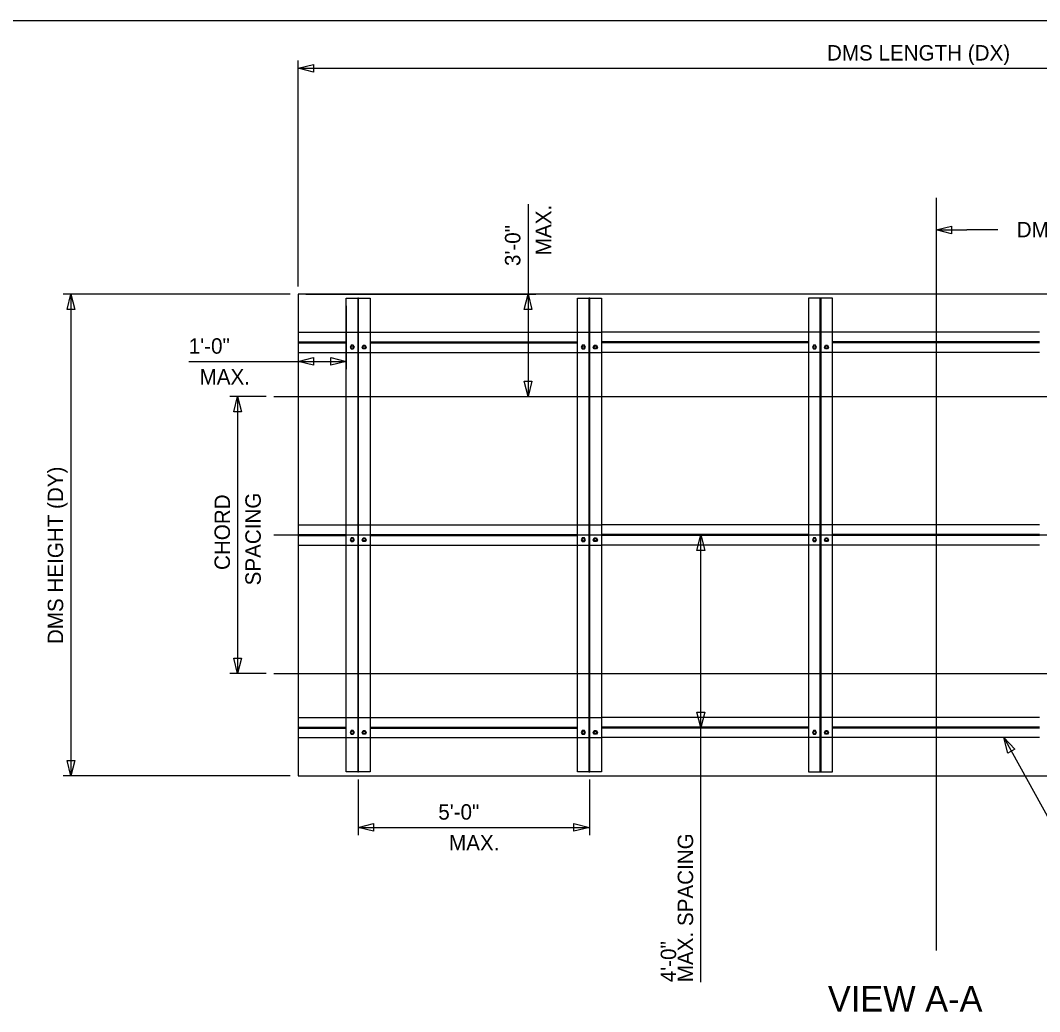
# Model space of a CAD drawing. Extents: x 3831399 to 3833095, y 499014 to 500202.
# Drawn here: x 3832479.3 to 3832677.7, y 499400.1 to 499593 of the extents above; entities that cross this region are included whole.
import ezdxf

# ---------------------------------------------------------------- set-up
doc = ezdxf.new("R2010")
doc.units = 0
for name, color, linetype in [('0-ANCHOR', 7, 'Continuous'), ('2', 7, 'Continuous'), ('CNTR', 7, 'Continuous'), ('Default', 7, 'Continuous'), ('DIM TXT', 7, 'Continuous'), ('sign', 7, 'Continuous'), ('structure', 7, 'Continuous')]:
    doc.layers.add(name, color=color, linetype=linetype)

msp = doc.modelspace()

# ---------------------------------------------------------------- linework, layer by layer
at = {"layer": '0-ANCHOR'}
for p, q in [((3832543.64, 499529.81), (3832543.44, 499529.45)), ((3832543.44, 499529.45), (3832543.64, 499529.09)), ((3832544.06, 499529.81), (3832543.64, 499529.81)), ((3832543.64, 499529.09), (3832544.06, 499529.09)), ((3832544.27, 499529.45), (3832544.06, 499529.81)), ((3832544.06, 499529.09), (3832544.27, 499529.45)), ((3832545.77, 499529.45), (3832545.98, 499529.81)), ((3832545.98, 499529.09), (3832545.77, 499529.45)), ((3832545.98, 499529.81), (3832546.4, 499529.81)), ((3832546.4, 499529.09), (3832545.98, 499529.09)), ((3832546.4, 499529.81), (3832546.6, 499529.45)), ((3832546.6, 499529.45), (3832546.4, 499529.09)), ((3832588.64, 499529.81), (3832588.44, 499529.45)), ((3832588.44, 499529.45), (3832588.64, 499529.09)), ((3832589.06, 499529.81), (3832588.64, 499529.81)), ((3832588.64, 499529.09), (3832589.06, 499529.09)), ((3832589.27, 499529.45), (3832589.06, 499529.81)), ((3832589.06, 499529.09), (3832589.27, 499529.45)), ((3832590.77, 499529.45), (3832590.98, 499529.81)), ((3832590.98, 499529.09), (3832590.77, 499529.45)), ((3832590.98, 499529.81), (3832591.39, 499529.81)), ((3832591.39, 499529.09), (3832590.98, 499529.09)), ((3832591.39, 499529.81), (3832591.6, 499529.45)), ((3832591.6, 499529.45), (3832591.39, 499529.09)), ((3832633.64, 499529.81), (3832633.43, 499529.45)), ((3832633.43, 499529.45), (3832633.64, 499529.09)), ((3832634.06, 499529.81), (3832633.64, 499529.81)), ((3832633.64, 499529.09), (3832634.06, 499529.09)), ((3832634.26, 499529.45), (3832634.06, 499529.81)), ((3832634.06, 499529.09), (3832634.26, 499529.45)), ((3832635.77, 499529.45), (3832635.98, 499529.81)), ((3832635.98, 499529.09), (3832635.77, 499529.45)), ((3832635.98, 499529.81), (3832636.39, 499529.81)), ((3832636.39, 499529.09), (3832635.98, 499529.09)), ((3832636.39, 499529.81), (3832636.6, 499529.45)), ((3832636.6, 499529.45), (3832636.39, 499529.09)), ((3832543.64, 499492.31), (3832543.44, 499491.95)), ((3832543.44, 499491.95), (3832543.64, 499491.59)), ((3832544.06, 499492.31), (3832543.64, 499492.31)), ((3832543.64, 499491.59), (3832544.06, 499491.59)), ((3832544.27, 499491.95), (3832544.06, 499492.31)), ((3832544.06, 499491.59), (3832544.27, 499491.95)), ((3832545.77, 499491.95), (3832545.98, 499492.31)), ((3832545.98, 499491.59), (3832545.77, 499491.95)), ((3832545.98, 499492.31), (3832546.4, 499492.31)), ((3832546.4, 499491.59), (3832545.98, 499491.59)), ((3832546.4, 499492.31), (3832546.6, 499491.95)), ((3832546.6, 499491.95), (3832546.4, 499491.59)), ((3832588.64, 499492.31), (3832588.44, 499491.95)), ((3832588.44, 499491.95), (3832588.64, 499491.59)), ((3832589.06, 499492.31), (3832588.64, 499492.31)), ((3832588.64, 499491.59), (3832589.06, 499491.59)), ((3832589.27, 499491.95), (3832589.06, 499492.31)), ((3832589.06, 499491.59), (3832589.27, 499491.95)), ((3832590.77, 499491.95), (3832590.98, 499492.31)), ((3832590.98, 499491.59), (3832590.77, 499491.95)), ((3832590.98, 499492.31), (3832591.39, 499492.31)), ((3832591.39, 499491.59), (3832590.98, 499491.59)), ((3832591.39, 499492.31), (3832591.6, 499491.95)), ((3832591.6, 499491.95), (3832591.39, 499491.59)), ((3832633.64, 499492.31), (3832633.43, 499491.95)), ((3832633.43, 499491.95), (3832633.64, 499491.59)), ((3832634.06, 499492.31), (3832633.64, 499492.31)), ((3832633.64, 499491.59), (3832634.06, 499491.59)), ((3832634.26, 499491.95), (3832634.06, 499492.31)), ((3832634.06, 499491.59), (3832634.26, 499491.95)), ((3832635.77, 499491.95), (3832635.98, 499492.31)), ((3832635.98, 499491.59), (3832635.77, 499491.95)), ((3832635.98, 499492.31), (3832636.39, 499492.31)), ((3832636.39, 499491.59), (3832635.98, 499491.59)), ((3832636.39, 499492.31), (3832636.6, 499491.95)), ((3832636.6, 499491.95), (3832636.39, 499491.59)), ((3832543.64, 499454.81), (3832543.44, 499454.45)), ((3832543.44, 499454.45), (3832543.64, 499454.09)), ((3832544.06, 499454.81), (3832543.64, 499454.81)), ((3832543.64, 499454.09), (3832544.06, 499454.09)), ((3832544.27, 499454.45), (3832544.06, 499454.81)), ((3832544.06, 499454.09), (3832544.27, 499454.45)), ((3832545.77, 499454.45), (3832545.98, 499454.81)), ((3832545.98, 499454.09), (3832545.77, 499454.45)), ((3832545.98, 499454.81), (3832546.4, 499454.81)), ((3832546.4, 499454.09), (3832545.98, 499454.09)), ((3832546.4, 499454.81), (3832546.6, 499454.45)), ((3832546.6, 499454.45), (3832546.4, 499454.09)), ((3832588.64, 499454.81), (3832588.44, 499454.45)), ((3832588.44, 499454.45), (3832588.64, 499454.09)), ((3832589.06, 499454.81), (3832588.64, 499454.81)), ((3832588.64, 499454.09), (3832589.06, 499454.09)), ((3832589.27, 499454.45), (3832589.06, 499454.81)), ((3832589.06, 499454.09), (3832589.27, 499454.45)), ((3832590.77, 499454.45), (3832590.98, 499454.81)), ((3832590.98, 499454.09), (3832590.77, 499454.45)), ((3832590.98, 499454.81), (3832591.39, 499454.81)), ((3832591.39, 499454.09), (3832590.98, 499454.09)), ((3832591.39, 499454.81), (3832591.6, 499454.45)), ((3832591.6, 499454.45), (3832591.39, 499454.09)), ((3832633.64, 499454.81), (3832633.43, 499454.45)), ((3832633.43, 499454.45), (3832633.64, 499454.09)), ((3832634.06, 499454.81), (3832633.64, 499454.81)), ((3832633.64, 499454.09), (3832634.06, 499454.09)), ((3832634.26, 499454.45), (3832634.06, 499454.81)), ((3832634.06, 499454.09), (3832634.26, 499454.45)), ((3832635.77, 499454.45), (3832635.98, 499454.81)), ((3832635.98, 499454.09), (3832635.77, 499454.45)), ((3832635.98, 499454.81), (3832636.39, 499454.81)), ((3832636.39, 499454.09), (3832635.98, 499454.09)), ((3832636.39, 499454.81), (3832636.6, 499454.45)), ((3832636.6, 499454.45), (3832636.39, 499454.09))]:
    msp.add_line(p, q, dxfattribs=at)
for centre in [(3832543.85, 499529.45), (3832546.19, 499529.45), (3832588.85, 499529.45), (3832591.19, 499529.45), (3832633.85, 499529.45), (3832636.19, 499529.45), (3832543.85, 499491.95), (3832546.19, 499491.95), (3832588.85, 499491.95), (3832591.19, 499491.95), (3832633.85, 499491.95), (3832636.19, 499491.95), (3832543.85, 499454.45), (3832546.19, 499454.45), (3832588.85, 499454.45), (3832591.19, 499454.45), (3832633.85, 499454.45), (3832636.19, 499454.45)]:
    msp.add_circle(centre, 0.244, dxfattribs=at)
at = {"layer": '2'}
msp.add_line((3832280.16, 499593.03), (3833066.16, 499593.03), dxfattribs=at)
at = {"layer": 'CNTR'}
for p, q in [((3832657.52, 499558.5), (3832657.52, 499411.97)), ((3832528.61, 499519.83), (3832815.35, 499519.83)), ((3832528.61, 499492.88), (3832829.18, 499492.88)), ((3832528.61, 499465.92), (3832815.12, 499465.92))]:
    msp.add_line(p, q, dxfattribs=at)
at = {"layer": 'DIM TXT'}
for p, q in [((3832533.3, 499541.25), (3832533.3, 499585.22)), ((3832533.3, 499583.72), (3832781.73, 499583.72)), ((3832578.09, 499557.29), (3832578.09, 499539.75)), ((3832657.52, 499552.25), (3832663.52, 499552.25)), ((3832669.52, 499552.25), (3832663.52, 499552.25)), ((3832531.8, 499539.75), (3832487.58, 499539.75)), ((3832489.08, 499539.75), (3832489.08, 499446)), ((3832534.8, 499539.75), (3832579.59, 499539.75)), ((3832578.09, 499539.75), (3832578.09, 499519.83)), ((3832542.68, 499537.47), (3832542.68, 499525.16)), ((3832533.31, 499530.83), (3832533.31, 499525.16)), ((3832512.04, 499526.66), (3832533.31, 499526.66)), ((3832533.31, 499526.66), (3832542.68, 499526.66)), ((3832527.11, 499519.83), (3832520.05, 499519.83)), ((3832521.55, 499519.83), (3832521.55, 499465.92)), ((3832534.8, 499519.83), (3832579.59, 499519.83)), ((3832631.18, 499492.88), (3832610.22, 499492.88)), ((3832611.72, 499455.38), (3832611.72, 499492.88)), ((3832527.11, 499465.92), (3832520.05, 499465.92)), ((3832631.18, 499455.38), (3832610.22, 499455.38)), ((3832611.72, 499405.83), (3832611.72, 499455.38)), ((3832670.7, 499453.43), (3832681.24, 499434.48)), ((3832531.8, 499446), (3832487.58, 499446)), ((3832545.02, 499445.28), (3832545.02, 499434.47)), ((3832590.02, 499445.28), (3832590.02, 499434.47)), ((3832545.02, 499435.97), (3832590.02, 499435.97))]:
    msp.add_line(p, q, dxfattribs=at)
for points in [[(3832536.3, 499582.97), (3832533.3, 499583.72), (3832536.3, 499584.47)], [(3832660.52, 499551.5), (3832657.52, 499552.25), (3832660.52, 499553)], [(3832488.33, 499536.75), (3832489.08, 499539.75), (3832489.83, 499536.75)], [(3832577.34, 499536.75), (3832578.09, 499539.75), (3832578.84, 499536.75)], [(3832536.31, 499525.91), (3832533.31, 499526.66), (3832536.31, 499527.41)], [(3832539.68, 499527.41), (3832542.68, 499526.66), (3832539.68, 499525.91)], [(3832578.84, 499522.83), (3832578.09, 499519.83), (3832577.34, 499522.83)], [(3832520.8, 499516.83), (3832521.55, 499519.83), (3832522.3, 499516.83)], [(3832610.97, 499489.88), (3832611.72, 499492.88), (3832612.47, 499489.88)], [(3832522.3, 499468.92), (3832521.55, 499465.92), (3832520.8, 499468.92)], [(3832612.47, 499458.38), (3832611.72, 499455.38), (3832610.97, 499458.38)], [(3832671.51, 499450.44), (3832670.7, 499453.43), (3832672.82, 499451.17)], [(3832489.83, 499449), (3832489.08, 499446), (3832488.33, 499449)], [(3832548.02, 499435.22), (3832545.02, 499435.97), (3832548.02, 499436.72)], [(3832587.02, 499436.72), (3832590.02, 499435.97), (3832587.02, 499435.22)]]:
    msp.add_lwpolyline(points, close=True, dxfattribs=at)
at = {"layer": 'sign'}
for p, q in [((3832781.73, 499539.75), (3832533.3, 499539.75)), ((3832533.3, 499539.75), (3832533.3, 499446)), ((3832533.31, 499532.33), (3832533.31, 499528.42)), ((3832533.31, 499532.33), (3832542.68, 499532.33)), ((3832542.68, 499532.33), (3832547.36, 499532.33)), ((3832547.36, 499532.33), (3832587.68, 499532.33)), ((3832587.68, 499532.33), (3832592.36, 499532.33)), ((3832632.68, 499532.33), (3832592.36, 499532.33)), ((3832637.36, 499532.33), (3832632.68, 499532.33)), ((3832677.68, 499532.33), (3832637.36, 499532.33)), ((3832533.31, 499530.47), (3832542.68, 499530.47)), ((3832533.31, 499530.28), (3832542.68, 499530.28)), ((3832547.36, 499530.47), (3832587.68, 499530.47)), ((3832547.36, 499530.28), (3832587.68, 499530.28)), ((3832632.68, 499530.47), (3832592.36, 499530.47)), ((3832632.68, 499530.28), (3832592.36, 499530.28)), ((3832677.68, 499530.47), (3832637.36, 499530.47)), ((3832677.68, 499530.28), (3832637.36, 499530.28)), ((3832533.31, 499528.42), (3832542.68, 499528.42)), ((3832542.68, 499528.42), (3832547.36, 499528.42)), ((3832547.36, 499528.42), (3832587.68, 499528.42)), ((3832587.68, 499528.42), (3832592.36, 499528.42)), ((3832632.68, 499528.42), (3832592.36, 499528.42)), ((3832637.36, 499528.42), (3832632.68, 499528.42)), ((3832677.68, 499528.42), (3832637.36, 499528.42)), ((3832533.31, 499494.83), (3832533.31, 499490.92)), ((3832533.31, 499494.83), (3832542.68, 499494.83)), ((3832542.68, 499494.83), (3832547.36, 499494.83)), ((3832547.36, 499494.83), (3832587.68, 499494.83)), ((3832587.68, 499494.83), (3832592.36, 499494.83)), ((3832632.68, 499494.83), (3832592.36, 499494.83)), ((3832637.36, 499494.83), (3832632.68, 499494.83)), ((3832677.68, 499494.83), (3832637.36, 499494.83)), ((3832533.31, 499492.97), (3832542.68, 499492.97)), ((3832533.31, 499492.78), (3832542.68, 499492.78)), ((3832547.36, 499492.97), (3832587.68, 499492.97)), ((3832547.36, 499492.78), (3832587.68, 499492.78)), ((3832632.68, 499492.97), (3832592.36, 499492.97)), ((3832632.68, 499492.78), (3832592.36, 499492.78)), ((3832677.68, 499492.97), (3832637.36, 499492.97)), ((3832677.68, 499492.78), (3832637.36, 499492.78)), ((3832533.31, 499490.92), (3832542.68, 499490.92)), ((3832542.68, 499490.92), (3832547.36, 499490.92)), ((3832547.36, 499490.92), (3832587.68, 499490.92)), ((3832587.68, 499490.92), (3832592.36, 499490.92)), ((3832632.68, 499490.92), (3832592.36, 499490.92)), ((3832637.36, 499490.92), (3832632.68, 499490.92)), ((3832677.68, 499490.92), (3832637.36, 499490.92)), ((3832533.31, 499457.33), (3832533.31, 499453.43)), ((3832533.31, 499457.33), (3832542.68, 499457.33)), ((3832533.31, 499455.48), (3832542.68, 499455.48)), ((3832542.68, 499457.33), (3832547.36, 499457.33)), ((3832547.36, 499457.33), (3832587.68, 499457.33)), ((3832547.36, 499455.48), (3832587.68, 499455.48)), ((3832587.68, 499457.33), (3832592.36, 499457.33)), ((3832632.68, 499457.33), (3832592.36, 499457.33)), ((3832632.68, 499455.48), (3832592.36, 499455.48)), ((3832637.36, 499457.33), (3832632.68, 499457.33)), ((3832677.68, 499457.33), (3832637.36, 499457.33)), ((3832677.68, 499455.48), (3832637.36, 499455.48)), ((3832533.31, 499455.28), (3832542.68, 499455.28)), ((3832547.36, 499455.28), (3832587.68, 499455.28)), ((3832632.68, 499455.28), (3832592.36, 499455.28)), ((3832677.68, 499455.28), (3832637.36, 499455.28)), ((3832533.31, 499453.43), (3832542.68, 499453.43)), ((3832542.68, 499453.43), (3832547.36, 499453.43)), ((3832547.36, 499453.43), (3832587.68, 499453.43)), ((3832587.68, 499453.43), (3832592.36, 499453.43)), ((3832632.68, 499453.43), (3832592.36, 499453.43)), ((3832637.36, 499453.43), (3832632.68, 499453.43)), ((3832677.68, 499453.43), (3832637.36, 499453.43)), ((3832533.3, 499446), (3832781.73, 499446))]:
    msp.add_line(p, q, dxfattribs=at)
at = {"layer": 'structure'}
for p, q in [((3832542.68, 499538.97), (3832547.36, 499538.97)), ((3832542.68, 499446.78), (3832542.68, 499538.97)), ((3832545.11, 499538.97), (3832544.93, 499538.97)), ((3832544.93, 499538.97), (3832544.93, 499446.78)), ((3832545.11, 499446.78), (3832545.11, 499538.97)), ((3832547.36, 499538.97), (3832547.36, 499446.78)), ((3832587.68, 499538.97), (3832592.36, 499538.97)), ((3832587.68, 499446.78), (3832587.68, 499538.97)), ((3832590.11, 499538.97), (3832589.93, 499538.97)), ((3832589.93, 499538.97), (3832589.93, 499446.78)), ((3832590.11, 499446.78), (3832590.11, 499538.97)), ((3832592.36, 499538.97), (3832592.36, 499446.78)), ((3832637.36, 499538.97), (3832632.68, 499538.97)), ((3832632.68, 499538.97), (3832632.68, 499446.78)), ((3832634.93, 499538.97), (3832635.11, 499538.97)), ((3832634.93, 499446.78), (3832634.93, 499538.97)), ((3832635.11, 499538.97), (3832635.11, 499446.78)), ((3832637.36, 499446.78), (3832637.36, 499538.97)), ((3832547.36, 499446.78), (3832542.68, 499446.78)), ((3832544.93, 499446.78), (3832545.11, 499446.78)), ((3832592.36, 499446.78), (3832587.68, 499446.78)), ((3832589.93, 499446.78), (3832590.11, 499446.78)), ((3832632.68, 499446.78), (3832637.36, 499446.78)), ((3832635.11, 499446.78), (3832634.93, 499446.78))]:
    msp.add_line(p, q, dxfattribs=at)

# ---------------------------------------------------------------- texts
at = {"layer": 'Default'}
msp.add_text('VIEW A-A', height=5, dxfattribs=at).set_placement((3832636.46, 499400.11))
at = {"layer": 'DIM TXT'}
for s, height, p in [('DMS LENGTH (DX)', 2.9999, (3832636.28, 499585.22)), ('  DMS', 3, (3832670.99, 499550.81)), ('1\'-0"', 3, (3832512.04, 499528.16)), ('MAX.', 3, (3832514.14, 499522.16)), ('5\'-0"', 3, (3832560.61, 499437.47)), ('MAX.', 3, (3832562.71, 499431.47))]:
    msp.add_text(s, height=height, dxfattribs=at).set_placement(p)
for s, height, p in [('MAX.', 3, (3832582.59, 499547.32)), ('3\'-0"', 3, (3832576.59, 499545.22)), ('DMS HEIGHT (DY)', 2.9999, (3832487.58, 499471.64)), ('CHORD', 3, (3832520.05, 499486.06)), ('SPACING', 3, (3832526.05, 499483.06)), ('MAX. SPACING', 2.9999, (3832610.22, 499405.83)), ('4\'-0"', 3, (3832606.91, 499405.83))]:
    msp.add_text(s, height=height, rotation=90, dxfattribs=at).set_placement(p)

doc.saveas('drawing.dxf')
